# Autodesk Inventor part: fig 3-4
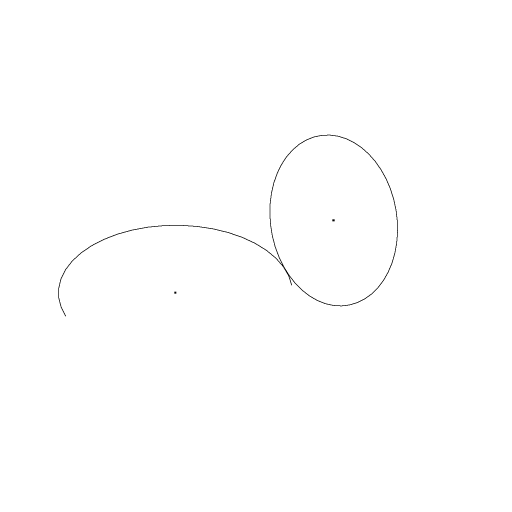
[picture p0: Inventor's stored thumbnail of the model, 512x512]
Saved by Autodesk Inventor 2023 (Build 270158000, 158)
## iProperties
Created: 2009-11
Part Number: fig 3-4
Document SubType Name: Modeling
Designer: Sham
Density: 1 g/cm^3
Material: Generic
Appearance: Default
Author: Sham
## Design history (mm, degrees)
sketch "Sketch1"
  geometry: A1 r 10.623 centre (-1.113, -21.203) between (5.463, -12.861) and (-5.537, -30.861); 1 further point; 1 other entity
  constraints: 2 point on circle, 1 centre point, 4 other
